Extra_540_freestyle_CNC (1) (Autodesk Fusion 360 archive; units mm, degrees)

design "Extra_540_freestyle_CNC" references "Extra_540_freeform v17_Fuselage_R", "Extra_540_freeform v17_Fuselage_L", "Extra_540_freeform v17_Wings_freestyle"
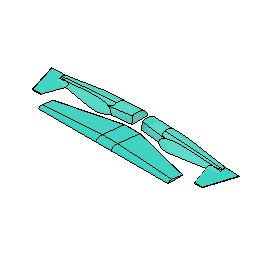
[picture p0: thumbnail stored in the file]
component_insert "Component Insert4"
component_insert "Component Insert5"
component_insert "Component Insert6"
ground "Ground2"
joint "Assemble1" OffsetX 0 OffsetY 0 OffsetZ 0 AngleZ 0 OffsetX 0 OffsetY 0 OffsetZ 0 AngleZ 0 alignAngle 0 alignOffsetX 5 alignOffsetY 8 alignOffsetZ 0
joint "Assemble2" OffsetX 0 OffsetY 0 OffsetZ 0 AngleZ 0 OffsetX 0 OffsetY 0 OffsetZ 0 AngleZ 0 alignAngle 180 alignOffsetX 12 alignOffsetY 6 alignOffsetZ 0

design "Extra_540_freeform v17_Fuselage_R"
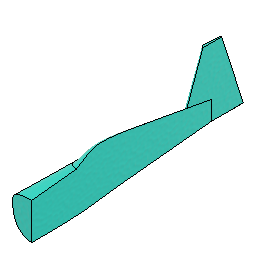
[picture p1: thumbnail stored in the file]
base_feature "Base Feature"
surface_delete_face "SurfaceDeleteFace1"
surface_patch "SurfacePatch1"
boundary_fill "BoundaryFill1"
sketch "Sketch1" plane through (0, 0, 0) normal (1, 0, 0) x axis (0, 0, -1)
work_plane "WorkPlane1" AlongDistance -7.633
sketch "Sketch2" plane through (0, -7.633, 0) normal (0, 1, 0) x axis (1, 0, 0)
  dimension "d128" = 1
  dimension "d129" = 7
work_plane "WorkPlane2" AlongDistance 55.351
sketch "Sketch3" plane through (0, 47.718, 0) normal (0, 1, 0) x axis (1, 0, 0)
  dimension "d133" = 4
  dimension "d135" = 8.5
  dimension "d136" = 1
  dimension "d137" = 1
  dimension "d138" = 4.8
loft "Loft1" sketch "Sketch2" + "Sketch3"
fillet "Fillet1" radius 1
sketch "Sketch4" plane through (0, 0, 0) normal (0, 1, 0) x axis (1, 0, 0)
extrude "Extrude1" cut sketch "Sketch4" no distance stored

design "Extra_540_freeform v17_Wings_freestyle"
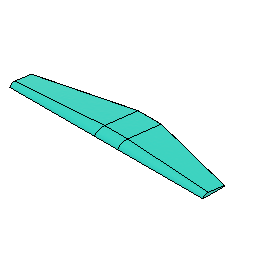
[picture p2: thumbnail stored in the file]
sketch "Sketch1" plane through (0, 0, 0) normal (1, 0, 0) x axis (0, 0, -1)
  dimension "d105" = 1
  dimension "d107" = 2
  dimension "d108" = 61
  dimension "d109" = 56
  dimension "d110" = 6.5
  dimension "d111" = 11
extrude "Extrude1" new body sketch "Sketch1" distance 15
sketch "Sketch4" plane through (0, -2, 0) normal (0, -1, 0) x axis (1, 0, 0)
  dimension "d123" = 110
work_plane "WorkPlane1" AlongDistance 110
sketch "Sketch2" plane through (125, 1.1412, -88.9996) normal (1, 0, 0) x axis (0, 0, -1)
  dimension "d124" = 4
  dimension "d125" = 1
loft "Loft1" sketch "Sketch2"
mirror "Mirror1"

design "Extra_540_freeform v17_Fuselage_L"
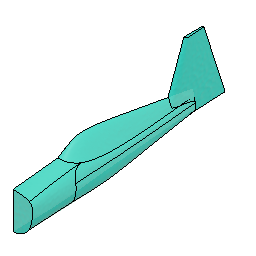
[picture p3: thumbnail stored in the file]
base_feature "Base Feature"
surface_delete_face "SurfaceDeleteFace1"
surface_patch "SurfacePatch1"
boundary_fill "BoundaryFill1"
sketch "Sketch1" plane through (0, 0, 0) normal (1, 0, 0) x axis (0, 0, -1)
work_plane "WorkPlane1" AlongDistance -7.633
sketch "Sketch2" plane through (0, -7.633, 0) normal (0, 1, 0) x axis (1, 0, 0)
  dimension "d128" = 1
  dimension "d129" = 7
work_plane "WorkPlane2" AlongDistance 55.351
sketch "Sketch3" plane through (0, 47.718, 0) normal (0, 1, 0) x axis (1, 0, 0)
  dimension "d133" = 4
  dimension "d135" = 8.5
  dimension "d136" = 1
  dimension "d137" = 1
  dimension "d138" = 4.8
loft "Loft1" sketch "Sketch2" + "Sketch3"
fillet "Fillet1" radius 1
sketch "Sketch4" plane through (0, 0, 0) normal (0, 1, 0) x axis (1, 0, 0)
extrude "Extrude1" cut sketch "Sketch4" no distance stored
